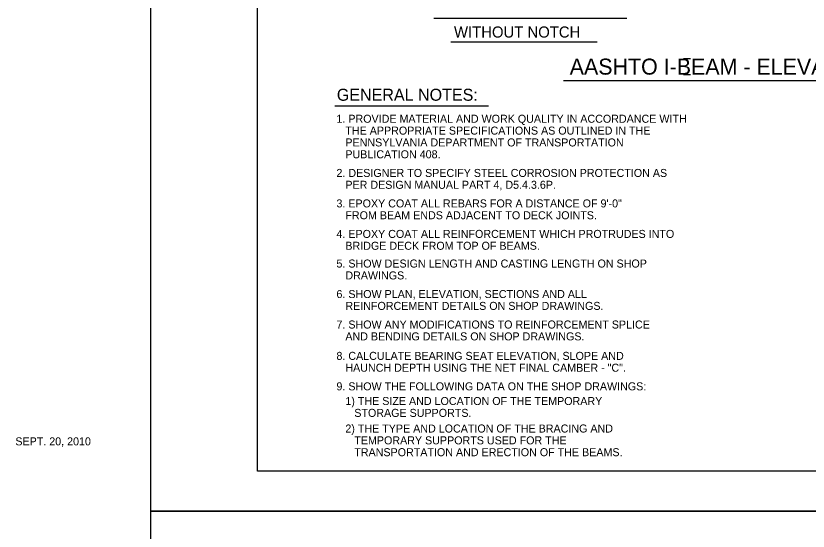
# Model space of a CAD drawing. Extents: x 637933 to 640019, y 298854 to 300042.
# Drawn here: x 637933.3 to 638230.3, y 299440.6 to 299633.7 of the extents above; entities that cross this region are included whole.
import ezdxf

# ---------------------------------------------------------------- set-up
doc = ezdxf.new("R2010")
doc.units = 0
doc.layers.add('1', color=7, linetype='Continuous')
doc.layers.add('PLT-BNDY', color=7, linetype='Continuous')

msp = doc.modelspace()

# ---------------------------------------------------------------- linework, layer by layer
at = {"layer": '1'}
for p, q in [((638023.93, 299463.12), (638023.93, 300027.12)), ((638162.27, 299632.76), (638089.97, 299632.76)), ((638151.2, 299623.89), (638096.36, 299623.89)), ((638183.6, 299617.69), (638186.2, 299617.69)), ((638183.6, 299611.68), (638186.2, 299611.68)), ((638291.96, 299609.31), (638138.54, 299609.31)), ((638052.94, 299600.02), (638110.42, 299600.02)), ((638809.94, 299463.12), (638023.93, 299463.12))]:
    msp.add_line(p, q, dxfattribs=at)
at = {"layer": 'PLT-BNDY'}
for points in [[(637983.93, 300042.12), (638824.93, 300042.12), (638824.93, 299448.12), (637983.93, 299448.12)], [(637983.93, 299448.12), (638824.93, 299448.12), (638824.93, 298854.12), (637983.93, 298854.12)]]:
    msp.add_lwpolyline(points, close=True, dxfattribs=at)

# ---------------------------------------------------------------- texts
at = {"layer": '1'}
for s, height, p in [('WITHOUT NOTCH', 4.1665, (638097.54, 299625.57)), ('AASHTO I-BEAM - ELEVATION', 6, (638140.91, 299611.69)), ('GENERAL NOTES:', 4.5, (638053.63, 299601.9)), (' 1. PROVIDE MATERIAL AND WORK QUALITY IN ACCORDANCE WITH', 3, (638052.37, 299593.66)), ('    THE APPROPRIATE SPECIFICATIONS AS OUTLINED IN THE', 3, (638052.37, 299589.22)), ('    PENNSYLVANIA DEPARTMENT OF TRANSPORTATION ', 3, (638052.37, 299584.78)), ('    PUBLICATION 408.', 3, (638052.37, 299580.34)), (' 2. DESIGNER TO SPECIFY STEEL CORROSION PROTECTION AS', 3, (638052.37, 299573.35)), ('    PER DESIGN MANUAL PART 4, D5.4.3.6P.', 3, (638052.37, 299568.91)), (' 3. EPOXY COAT ALL REBARS FOR A DISTANCE OF 9\'-0"', 3, (638052.37, 299561.93)), ('    FROM BEAM ENDS ADJACENT TO DECK JOINTS.', 3, (638052.37, 299557.49)), (' 4. EPOXY COAT ALL REINFORCEMENT WHICH PROTRUDES INTO', 3, (638052.37, 299550.5)), ('    BRIDGE DECK FROM TOP OF BEAMS.', 3, (638052.37, 299546.06)), (' 5. SHOW DESIGN LENGTH AND CASTING LENGTH ON SHOP', 3, (638052.37, 299539.4)), ('    DRAWINGS.', 3, (638052.37, 299534.95)), (' 6. SHOW PLAN, ELEVATION, SECTIONS AND ALL', 3, (638052.37, 299527.97)), ('    REINFORCEMENT DETAILS ON SHOP DRAWINGS.', 3, (638052.37, 299523.53)), (' 7. SHOW ANY MODIFICATIONS TO REINFORCEMENT SPLICE', 3, (638052.37, 299516.55)), ('    AND BENDING DETAILS ON SHOP DRAWINGS.', 3, (638052.37, 299512.1)), (' 8. CALCULATE BEARING SEAT ELEVATION, SLOPE AND', 3, (638052.37, 299504.8)), ('    HAUNCH DEPTH USING THE NET FINAL CAMBER - "C".', 3, (638052.37, 299500.36)), (' 9. SHOW THE FOLLOWING DATA ON THE SHOP DRAWINGS:', 3, (638052.37, 299493.38)), ('    1) THE SIZE AND LOCATION OF THE TEMPORARY', 3, (638052.37, 299487.88)), ('       STORAGE SUPPORTS.', 3, (638052.37, 299483.44)), ('    2) THE TYPE AND LOCATION OF THE BRACING AND', 3, (638052.37, 299477.58)), ('SEPT. 20, 2010', 3, (637933.14, 299472.77)), ('       TEMPORARY SUPPORTS USED FOR THE', 3, (638052.37, 299473.14)), ('       TRANSPORTATION AND ERECTION OF THE BEAMS.', 3, (638052.37, 299468.7))]:
    msp.add_text(s, height=height, dxfattribs=at).set_placement(p)

doc.saveas('drawing.dxf')
